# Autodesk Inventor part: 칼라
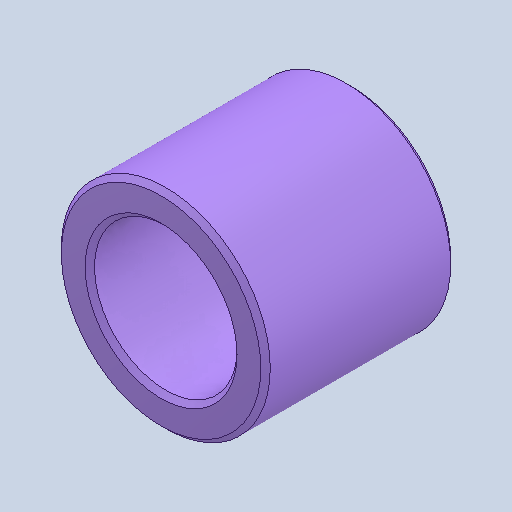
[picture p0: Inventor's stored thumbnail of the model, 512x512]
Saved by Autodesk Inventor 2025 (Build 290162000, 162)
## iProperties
Created: 2025-08
Part Number: 칼라
Material: 스테인리스강
Document SubType Name: Modeling
Designer: infra028
Density: 8.08 g/cm^3
Appearance: 기본값
Author: jhkim
Sending System: Autodesk Inventor 2026
Preprocessor: ST-DEVELOPER v20.1
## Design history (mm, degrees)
feature "솔리드1"
node "솔리드2"
